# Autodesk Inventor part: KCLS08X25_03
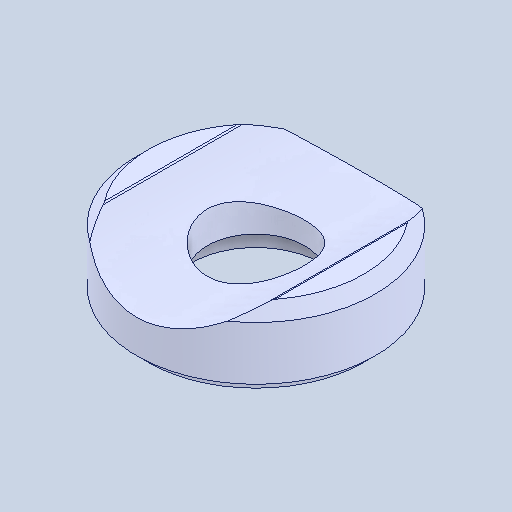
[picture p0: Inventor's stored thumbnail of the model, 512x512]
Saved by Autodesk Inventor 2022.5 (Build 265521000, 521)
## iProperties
Created: 2024-08
Part Number: KCLS08X25_03
Material: 一般
Document SubType Name: Modeling
Designer: ImaoCorp
Density: 1 g/cm^3
Appearance: 既定
Author: ImaoCorp
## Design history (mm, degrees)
feature "KCLS08X25_03"
node "ソリッド1"
